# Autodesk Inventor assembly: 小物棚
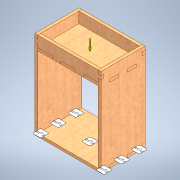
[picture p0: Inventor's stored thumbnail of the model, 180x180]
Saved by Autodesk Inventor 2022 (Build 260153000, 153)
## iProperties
Created: 2024-11
Part Number: 小物棚
Document SubType Name: Assembly
Designer: shimizu
Mass: 23.8 g
Surface Area: 271.6 cm^2
Volume: 29.75 cm^3
Density: 0.8 g/cm^3
Author: shimizu
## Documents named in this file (5)
- C:\Users\shimizu\Documents\卒論2024\3DCAD\小物棚\組立図\小物棚.iam
- C:\Users\shimizu\Documents\卒論2024\3DCAD\小物棚\部品図\底板.ipt
- C:\Users\shimizu\Documents\卒論2024\3DCAD\小物棚\部品図\側板.ipt
- C:\Users\shimizu\Documents\卒論2024\3DCAD\小物棚\部品図\天板.ipt
- C:\Users\shimizu\Documents\卒論2024\3DCAD\小物棚\部品図\側板②.ipt
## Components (6 placed, 4 different names)
1. 底板:1 — メイト:1, メイト:2, フラッシュ:1, メイト:3, フラッシュ:2, フラッシュ:3
2. 側板:1 — メイト:1, メイト:2, フラッシュ:1, フラッシュ:4, フラッシュ:6, フラッシュ:7, フラッシュ:10
3. 側板:2 — メイト:3, フラッシュ:2, フラッシュ:3, フラッシュ:5, メイト:4, フラッシュ:8, フラッシュ:9, メイト:5
4. 天板:1 — フラッシュ:4, フラッシュ:5, メイト:4
5. 側板②:1 — フラッシュ:6, フラッシュ:7, フラッシュ:8
6. 側板②:2 — フラッシュ:9, フラッシュ:10, メイト:5
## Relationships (15: Flush 10, Mate 5)
- メイト:1 [Mate]: 底板:1 ↔ 側板:1
- メイト:2 [Mate]: 底板:1 ↔ 側板:1
- フラッシュ:1 [Flush]: 底板:1 ↔ 側板:1
- メイト:3 [Mate]: 底板:1 ↔ 側板:2
- フラッシュ:2 [Flush]: 底板:1 ↔ 側板:2
- フラッシュ:3 [Flush]: 底板:1 ↔ 側板:2
- フラッシュ:4 [Flush]: 側板:1 ↔ 天板:1
- フラッシュ:5 [Flush]: 側板:2 ↔ 天板:1
- メイト:4 [Mate]: 側板:2 ↔ 天板:1
- フラッシュ:6 [Flush]: 側板:1 ↔ 側板②:1
- フラッシュ:7 [Flush]: 側板:1 ↔ 側板②:1
- フラッシュ:8 [Flush]: 側板:2 ↔ 側板②:1
- フラッシュ:9 [Flush]: 側板:2 ↔ 側板②:2
- フラッシュ:10 [Flush]: 側板:1 ↔ 側板②:2
- メイト:5 [Mate]: 側板:2 ↔ 側板②:2
## Named parameters: sa_0 = 190000 mm
